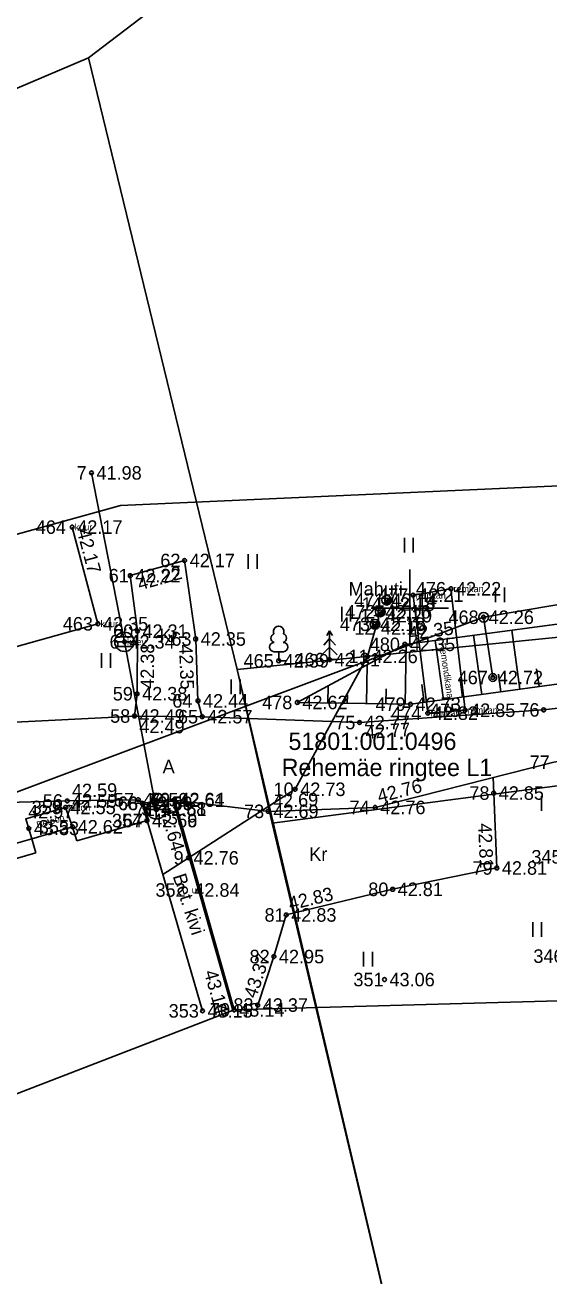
# Model space of a CAD drawing. Extents: x 505800 to 507326, y 6540058 to 6542128.
# Drawn here: x 506130.1 to 506157.2, y 6540215.4 to 6540280.2 of the extents above; entities that cross this region are included whole.
import ezdxf

# ---------------------------------------------------------------- set-up
doc = ezdxf.new("R2010")
doc.units = 0
for name, color, linetype in [('HALJASTUS', 7, 'Continuous'), ('HOONE', 7, 'Continuous'), ('HOONEDET', 7, 'Continuous'), ('KKAEV', 7, 'Continuous'), ('KORGUS-EH2000', 7, 'Continuous'), ('KTRASS', 7, 'Continuous'), ('MAAMUDEL', 7, 'Continuous'), ('MOOTKORG-EH2000', 7, 'Continuous'), ('MOOTMPUNKT', 7, 'Continuous'), ('MOOTNR', 7, 'Continuous'), ('MOOTPIIR', 7, 'Continuous'), ('MPOHULIIN', 7, 'Continuous'), ('PIIR', 7, 'Continuous'), ('POST', 7, 'Continuous'), ('PUU', 7, 'Continuous'), ('RAJATIS', 7, 'Continuous'), ('RELJEEF', 7, 'Continuous'), ('SKKAEV', 7, 'Continuous'), ('SKTRASS', 7, 'Continuous'), ('TEE', 7, 'Continuous'), ('VORK', 7, 'Continuous')]:
    doc.layers.add(name, color=color, linetype=linetype)

msp = doc.modelspace()

# ---------------------------------------------------------------- linework, layer by layer
at = {"layer": 'HALJASTUS'}
for p, q in [((506149.723, 6540253.631), (506149.723, 6540252.87)), ((506150.178, 6540253.631), (506150.178, 6540252.87)), ((506141.636, 6540252.79), (506141.636, 6540252.029)), ((506142.091, 6540252.79), (506142.091, 6540252.029)), ((506154.447, 6540251.067), (506154.447, 6540250.306)), ((506154.903, 6540251.067), (506154.903, 6540250.306)), ((506146.48, 6540250.066), (506146.48, 6540249.305)), ((506146.935, 6540250.066), (506146.935, 6540249.305)), ((506134.039, 6540247.662), (506134.039, 6540246.901)), ((506134.494, 6540247.662), (506134.494, 6540246.901)), ((506140.755, 6540246.3), (506140.755, 6540245.539)), ((506141.21, 6540246.3), (506141.21, 6540245.539)), ((506156.831, 6540240.242), (506156.831, 6540239.481)), ((506156.37, 6540233.722), (506156.37, 6540232.961)), ((506156.825, 6540233.722), (506156.825, 6540232.961)), ((506147.612, 6540232.18), (506147.612, 6540231.419)), ((506148.067, 6540232.18), (506148.067, 6540231.419))]:
    msp.add_line(p, q, dxfattribs=at)
at = {"layer": 'HOONE'}
for p, q in [((506132.539, 6540238.658), (506130.426, 6540238.044)), ((506132.539, 6540238.658), (506132.753, 6540237.924)), ((506130.426, 6540238.044), (506130.639, 6540237.309)), ((506130.639, 6540237.309), (506126.746, 6540236.177))]:
    msp.add_line(p, q, dxfattribs=at)
for points in [[(506132.518, 6540254.195), (506133.851, 6540249.184), (506123.465, 6540246.272), (506109.297, 6540242.297), (506097.771, 6540239.032), (506096.343, 6540244.043)], [(506132.753, 6540237.924), (506136.393, 6540238.982), (506139.264, 6540229.118)]]:
    msp.add_lwpolyline(points, dxfattribs=at)
at = {"layer": 'HOONEDET'}
msp.add_line((506125.837, 6540236.712), (506130.426, 6540238.044), dxfattribs=at)
at = {"layer": 'KKAEV'}
for p, q in [((506136.875, 6540239.064), (506136.875, 6540240.064)), ((506136.375, 6540239.564), (506137.375, 6540239.564))]:
    msp.add_line(p, q, dxfattribs=at)
msp.add_circle((506136.875, 6540239.564), 0.5, dxfattribs=at)
at = {"layer": 'KORGUS-EH2000'}
for centre in [(506133.515, 6540257.006), (506132.518, 6540254.195), (506138.341, 6540252.466), (506135.526, 6540251.679), (506152.137, 6540250.999), (506148.806, 6540250.407), (506150.181, 6540250.665), (506148.48, 6540249.801), (506133.851, 6540249.184), (506148.202, 6540249.16), (506153.828, 6540249.522), (506135.897, 6540248.799), (506138.913, 6540248.394), (506135.221, 6540248.25), (506149.749, 6540248.117), (506143.213, 6540247.263), (506145.85, 6540247.326), (506147.811, 6540247.492), (506154.303, 6540246.399), (506135.88, 6540245.556), (506139.032, 6540245.186), (506144.177, 6540245.106), (506150.046, 6540245.013), (506150.934, 6540244.549), (506152.867, 6540244.701), (506156.937, 6540244.719), (506135.743, 6540244.402), (506139.254, 6540244.367), (506147.401, 6540244.066), (506144.069, 6540240.604), (506132.254, 6540239.999), (506135.937, 6540240.063), (506137.811, 6540240.072), (506137.814, 6540240.039), (506154.348, 6540240.409), (506132.168, 6540239.664), (506136.14, 6540239.882), (506136.149, 6540239.864), (506136.86, 6540239.594), (506136.875, 6540239.564), (506142.677, 6540239.46), (506148.214, 6540239.664), (506132.539, 6540238.658), (506136.393, 6540238.982), (506136.395, 6540238.982), (506130.271, 6540238.577), (506138.541, 6540237.05), (506154.513, 6540236.525), (506149.115, 6540235.419), (506143.601, 6540234.09), (506142.965, 6540231.933), (506148.693, 6540230.741), (506139.264, 6540229.118), (506140.91, 6540229.168), (506142.127, 6540229.419)]:
    msp.add_circle(centre, 0.1, dxfattribs=at)
at = {"layer": 'KTRASS'}
msp.add_lwpolyline([(506148.371, 6540249.426), (506147.811, 6540247.492), (506144.069, 6540240.604), (506137.205, 6540236.191)], dxfattribs=at)
at = {"layer": 'MOOTMPUNKT'}
for centre in [(506133.515, 6540257.006), (506132.518, 6540254.195), (506138.341, 6540252.466), (506135.526, 6540251.679), (506152.137, 6540250.999), (506148.806, 6540250.407), (506150.181, 6540250.665), (506148.48, 6540249.801), (506133.851, 6540249.184), (506148.202, 6540249.16), (506153.828, 6540249.522), (506135.897, 6540248.799), (506138.913, 6540248.394), (506135.221, 6540248.25), (506149.749, 6540248.117), (506143.213, 6540247.263), (506145.85, 6540247.326), (506147.811, 6540247.492), (506154.303, 6540246.399), (506135.88, 6540245.556), (506139.032, 6540245.186), (506144.177, 6540245.106), (506150.046, 6540245.013), (506150.934, 6540244.549), (506152.867, 6540244.701), (506156.937, 6540244.719), (506135.743, 6540244.402), (506139.254, 6540244.367), (506147.401, 6540244.066), (506144.069, 6540240.604), (506132.254, 6540239.999), (506135.937, 6540240.063), (506137.811, 6540240.072), (506137.814, 6540240.039), (506154.348, 6540240.409), (506132.168, 6540239.664), (506136.14, 6540239.882), (506136.149, 6540239.864), (506136.86, 6540239.594), (506136.875, 6540239.564), (506142.677, 6540239.46), (506148.214, 6540239.664), (506132.539, 6540238.658), (506136.393, 6540238.982), (506136.395, 6540238.982), (506130.271, 6540238.577), (506138.541, 6540237.05), (506154.513, 6540236.525), (506149.115, 6540235.419), (506143.601, 6540234.09), (506142.965, 6540231.933), (506148.693, 6540230.741), (506139.264, 6540229.118), (506140.91, 6540229.168), (506142.127, 6540229.419)]:
    msp.add_circle(centre, 0.1, dxfattribs=at)
at = {"layer": 'MOOTPIIR'}
for points in [[(506083.03, 6540240.114), (506097.119, 6540244.795), (506135.023, 6540255.311), (506160.43, 6540256.455), (506171.091, 6540256.503), (506184.044, 6540258.184), (506197.806, 6540260.288), (506211.896, 6540262.383), (506227.932, 6540267.786), (506240.253, 6540270.959), (506245.955, 6540263.864)], [(506248.469, 6540250.071), (506234.931, 6540239.99), (506231.591, 6540236.406), (506193.196, 6540222.875), (506188.596, 6540225.549), (506168.901, 6540229.957), (506140.91, 6540229.168), (506108.07, 6540216.496), (506098.399, 6540223.506), (506079.917, 6540216.55)]]:
    msp.add_lwpolyline(points, dxfattribs=at)
at = {"layer": 'MPOHULIIN'}
msp.add_lwpolyline([(506112.189, 6540233.927), (506153.828, 6540249.522), (506196.936, 6540256.778), (506240.207, 6540264.027), (506283.784, 6540271.755), (506305.802, 6540315.044)], dxfattribs=at)
at = {"layer": 'PIIR'}
for points in [[(506133.36, 6540278.52), (506190.15, 6540321.81), (506215.95, 6540254.34), (506141.06, 6540246.81)], [(506075.94, 6540254.08), (506092.1, 6540260.96), (506133.36, 6540278.52), (506141.06, 6540246.81), (506150.17, 6540208.02), (506090.32, 6540182.64), (506081.75, 6540225.93), (506080.52, 6540231.87)]]:
    msp.add_lwpolyline(points, close=True, dxfattribs=at)
for points in [[(506272.39, 6540267.75), (506224.13, 6540249.92), (506208.53, 6540246.07), (506198.96, 6540244.45), (506187, 6540243.59), (506158.97, 6540240.95), (506142.88, 6540238.84), (506141.06, 6540246.81), (506215.95, 6540254.34), (506268.55, 6540273.9)], [(506028.99, 6540136.11), (506018.19, 6540200.68), (506049.36, 6540212.6), (506053.99, 6540200.79), (506052.51, 6540200.31), (506055.45, 6540190.69), (506062.61, 6540193.04), (506059.62, 6540202.68), (506057.79, 6540202.01), (506053.1, 6540214.07), (506081.75, 6540225.93), (506090.32, 6540182.64), (506150.17, 6540208.02), (506142.88, 6540238.84), (506158.97, 6540240.95), (506187, 6540243.59), (506198.96, 6540244.45), (506208.53, 6540246.07), (506224.13, 6540249.92), (506272.39, 6540267.75)]]:
    msp.add_lwpolyline(points, dxfattribs=at)
at = {"layer": 'POST'}
for p, q in [((506148.629, 6540250.23), (506148.983, 6540250.584)), ((506148.303, 6540249.625), (506148.657, 6540249.978)), ((506148.024, 6540248.984), (506148.378, 6540249.337))]:
    msp.add_line(p, q, dxfattribs=at)
msp.add_lwpolyline([(506154.303, 6540246.399), (506153.828, 6540249.522)], dxfattribs=at)
for centre, radius in [((506148.806, 6540250.407), 0.25), ((506148.48, 6540249.801), 0.25), ((506148.202, 6540249.16), 0.25), ((506153.828, 6540249.522), 0.25), ((506154.303, 6540246.399), 0.2)]:
    msp.add_circle(centre, radius, dxfattribs=at)
for centre, radius, start, end in [((506148.806, 6540250.407), 0.225, 224.85406, 45.03563), ((506148.806, 6540250.407), 0.2, 224.84272, 45.04698), ((506148.806, 6540250.407), 0.175, 224.82813, 45.06157), ((506148.806, 6540250.407), 0.15, 224.80867, 45.08103), ((506148.806, 6540250.407), 0.125, 224.78144, 45.10826), ((506148.806, 6540250.407), 0.1, 224.74058, 45.14911), ((506148.806, 6540250.407), 0.075, 224.67249, 45.2172), ((506148.806, 6540250.407), 0.05, 224.53632, 45.35338), ((506148.48, 6540249.801), 0.225, 224.85406, 45.03563), ((506148.48, 6540249.801), 0.2, 224.84272, 45.04698), ((506148.48, 6540249.801), 0.175, 224.82813, 45.06157), ((506148.48, 6540249.801), 0.15, 224.80867, 45.08103), ((506148.48, 6540249.801), 0.125, 224.78144, 45.10826), ((506148.48, 6540249.801), 0.1, 224.74058, 45.14911), ((506148.48, 6540249.801), 0.075, 224.67249, 45.2172), ((506148.48, 6540249.801), 0.05, 224.53632, 45.35338), ((506148.48, 6540249.801), 0.025, 224.12776, 45.76193), ((506148.806, 6540250.407), 0.025, 224.12776, 45.76193), ((506148.202, 6540249.16), 0.225, 224.85406, 45.03563), ((506148.202, 6540249.16), 0.2, 224.84272, 45.04698), ((506148.202, 6540249.16), 0.175, 224.82813, 45.06157), ((506148.202, 6540249.16), 0.15, 224.80867, 45.08103), ((506148.202, 6540249.16), 0.125, 224.78144, 45.10826), ((506148.202, 6540249.16), 0.1, 224.74058, 45.14911), ((506148.202, 6540249.16), 0.075, 224.67249, 45.2172), ((506148.202, 6540249.16), 0.05, 224.53632, 45.35338), ((506148.202, 6540249.16), 0.025, 224.12776, 45.76193)]:
    msp.add_arc(centre, radius, start, end, dxfattribs=at)
at = {"layer": 'PUU'}
for p, q in [((506145.85, 6540248.826), (506145.7, 6540248.576)), ((506146, 6540248.576), (506145.85, 6540248.826)), ((506145.85, 6540248.826), (506145.85, 6540247.326)), ((506145.85, 6540247.976), (506145.45, 6540247.576)), ((506145.85, 6540248.426), (506145.55, 6540248.076)), ((506146.15, 6540248.076), (506145.85, 6540248.426)), ((506146.25, 6540247.576), (506145.85, 6540247.976)), ((506143.454, 6540247.738), (506142.974, 6540247.738)), ((506143.213, 6540247.263), (506143.213, 6540247.738)), ((506143.594, 6540247.263), (506143.213, 6540247.263)), ((506146.21, 6540247.326), (506145.85, 6540247.326))]:
    msp.add_line(p, q, dxfattribs=at)
for centre, radius, start, end in [((506143.043, 6540248.436), 0.233, 109.02174, 253.14154), ((506143.213, 6540248.783), 0.277, 332.5799, 207.4201), ((506143.384, 6540248.436), 0.233, 286.85082, 70.98591), ((506142.976, 6540247.976), 0.238, 90.0016, 269.3953), ((506143.451, 6540247.976), 0.238, 270.6047, 89.9984)]:
    msp.add_arc(centre, radius, start, end, dxfattribs=at)
at = {"layer": 'RAJATIS'}
msp.add_lwpolyline([(506150.181, 6540250.665), (506150.934, 6540244.549), (506152.867, 6540244.701), (506152.137, 6540250.999)], close=True, dxfattribs=at)
at = {"layer": 'RELJEEF'}
for p, q in [((506153.727, 6540245.52), (506153.305, 6540248.587)), ((506155.708, 6540245.793), (506155.287, 6540248.85)), ((506149.762, 6540245.017), (506149.811, 6540248.125)), ((506151.746, 6540245.247), (506151.322, 6540248.325)), ((506147.762, 6540245.049), (506147.794, 6540247.061)), ((506154.718, 6540245.656), (506154.591, 6540246.575)), ((506156.699, 6540245.929), (506156.573, 6540246.845)), ((506145.762, 6540245.081), (506145.777, 6540245.971)), ((506150.755, 6540245.11), (506150.628, 6540246.036)), ((506152.736, 6540245.383), (506152.61, 6540246.305)), ((506146.762, 6540245.065), (506146.769, 6540245.5)), ((506148.762, 6540245.033), (506148.774, 6540245.805)), ((506144.763, 6540245.097), (506144.764, 6540245.196))]:
    msp.add_line(p, q, dxfattribs=at)
for points in [[(506186.229, 6540254.552), (506171.546, 6540250.385), (506161.646, 6540249.691), (506149.749, 6540248.117), (506144.177, 6540245.106)], [(506187.313, 6540250.618), (506176.15, 6540249.371), (506171.713, 6540248.272), (506161.906, 6540246.646), (506150.046, 6540245.013), (506144.177, 6540245.106)]]:
    msp.add_lwpolyline(points, dxfattribs=at)
at = {"layer": 'SKKAEV'}
for p, q in [((506135.651, 6540248.5), (506134.791, 6540248.5)), ((506134.721, 6540248.25), (506135.721, 6540248.25)), ((506135.651, 6540248), (506134.791, 6540248))]:
    msp.add_line(p, q, dxfattribs=at)
msp.add_circle((506135.221, 6540248.25), 0.5, dxfattribs=at)
at = {"layer": 'SKTRASS'}
msp.add_lwpolyline([(506133.515, 6540257.006), (506135.221, 6540248.25), (506136.86, 6540239.594)], dxfattribs=at)
at = {"layer": 'TEE'}
for points in [[(506250.031, 6540264.042), (506237.432, 6540259.066), (506223.872, 6540254.219), (506212.634, 6540251.013), (506200.022, 6540248.8), (506187.383, 6540247.629), (506174.426, 6540246.673), (506168.123, 6540246.063), (506162.988, 6540245.422), (506156.937, 6540244.719), (506147.401, 6540244.066), (506139.254, 6540244.367), (506135.743, 6540244.402), (506126.133, 6540243.916), (506116.327, 6540241.664), (506104.313, 6540238.326), (506099.073, 6540236.742), (506091.024, 6540234.378), (506084.768, 6540232.16)], [(506250.904, 6540261.782), (506238.366, 6540256.809), (506224.827, 6540251.952), (506213.198, 6540248.536), (506200.494, 6540246.321), (506187.779, 6540245.271), (506174.602, 6540244.231), (506168.346, 6540243.484), (506163.12, 6540242.933), (506157.471, 6540242.007), (506148.214, 6540239.664), (506142.677, 6540239.46), (506137.814, 6540240.039)], [(506139.254, 6540244.367), (506139.032, 6540245.186), (506138.913, 6540248.394), (506138.341, 6540252.466), (506135.526, 6540251.679), (506135.897, 6540248.799), (506135.88, 6540245.556), (506135.743, 6540244.402)], [(506142.127, 6540229.419), (506142.965, 6540231.933), (506143.601, 6540234.09), (506149.115, 6540235.419), (506154.513, 6540236.525), (506154.348, 6540240.409), (506154.329, 6540241.211)], [(506136.149, 6540239.864), (506135.937, 6540240.063), (506132.254, 6540239.999), (506126.638, 6540239.842), (506117.049, 6540238.049), (506105.059, 6540234.886), (506099.56, 6540233.572), (506092.451, 6540231.789), (506085.515, 6540229.625), (506076.748, 6540225.83), (506064.781, 6540220.419), (506053.702, 6540216.033), (506042.573, 6540211.964), (506030.369, 6540207.528), (506023.645, 6540204.818), (506020.115, 6540202.573), (506018.326, 6540200.153), (506016.859, 6540196.696), (506016.712, 6540193.498), (506017.316, 6540188.473)], [(506140.91, 6540229.168), (506137.811, 6540240.072), (506136.14, 6540239.882), (506136.395, 6540238.982)], [(506132.539, 6540238.658), (506132.168, 6540239.664), (506130.113, 6540239.081), (506130.426, 6540238.044)], [(506140.833, 6540229.146), (506137.752, 6540239.985), (506136.243, 6540239.813), (506136.472, 6540239.004), (506136.395, 6540238.982)]]:
    msp.add_lwpolyline(points, dxfattribs=at)
at = {"layer": 'VORK'}
for p, q in [((506150, 6540252), (506150, 6540248)), ((506148, 6540250), (506152, 6540250))]:
    msp.add_line(p, q, dxfattribs=at)

# ---------------------------------------------------------------- texts
at = {"layer": 'KORGUS-EH2000'}
for s, rotation, p in [(' 42.17', 284.89789, (506132.687, 6540254.24)), (' 42.22', 15.62715, (506135.762, 6540250.836)), (' 42.35', 7.53501, (506149.727, 6540248.291)), (' 42.38', 89.70843, (506136.755, 6540245.552)), (' 42.35', 272.12083, (506138.039, 6540248.362)), (' 42.49', 359.42558, (506135.734, 6540243.527)), (' 42.77', 3.91269, (506147.461, 6540243.193)), (' 42.59', 1.00192, (506132.251, 6540240.174)), (' 42.76', 14.19953, (506148.171, 6540239.834)), (' 42.69', 2.10984, (506142.67, 6540239.635)), (' 42.64', 285.86438, (506136.969, 6540239.833)), (' 42.81', 272.42534, (506153.528, 6540239.089)), (' 42.83', 13.54771, (506143.56, 6540234.261)), (' 43.37', 71.56642, (506141.961, 6540229.474)), (' 43.14', 285.86438, (506139.267, 6540231.378))]:
    msp.add_text(s, height=0.7, rotation=rotation, dxfattribs=at).set_placement(p)
for s, p in [(' 42.26', (506153.828, 6540249.172)), (' 42.39', (506143.213, 6540246.913)), (' 43.06', (506148.693, 6540230.391))]:
    msp.add_text(s, height=0.7, dxfattribs=at).set_placement(p)
at = {"layer": 'MAAMUDEL'}
for s, p in [(' kuur', (506132.518, 6540254.02)), (' remkan', (506152.137, 6540250.824)), (' remkan', (506150.181, 6540250.49)), (' kuur', (506133.851, 6540249.009)), (' kaev', (506135.221, 6540248.075)), (' remkan', (506150.934, 6540244.374)), (' remkan', (506152.867, 6540244.526)), (' beton', (506132.168, 6540239.489)), (' uk', (506138.581, 6540235.208))]:
    msp.add_text(s, height=0.35, dxfattribs=at).set_placement(p)
at = {"layer": 'MOOTKORG-EH2000'}
for s, p in [(' 41.98', (506133.515, 6540256.656)), (' 42.17', (506132.518, 6540253.845)), (' 42.17', (506138.341, 6540252.116)), (' 42.22', (506135.526, 6540251.329)), (' 42.22', (506152.137, 6540250.649)), (' 42.18', (506148.701, 6540249.855)), (' 42.14', (506148.806, 6540250.057)), (' 42.21', (506150.181, 6540250.315)), (' 42.16', (506148.48, 6540249.451)), (' 42.20', (506148.548, 6540249.252)), (' 42.26', (506153.828, 6540249.172)), (' 42.35', (506133.851, 6540248.834)), (' 42.31', (506135.897, 6540248.449)), (' 42.18', (506148.202, 6540248.81)), (' 42.19', (506148.254, 6540248.621)), (' 42.34', (506135.221, 6540247.9)), (' 42.35', (506138.913, 6540248.044)), (' 42.26', (506147.811, 6540247.142)), (' 42.35', (506149.749, 6540247.767)), (' 42.39', (506143.213, 6540246.913)), (' 42.31', (506145.85, 6540246.976)), (' 42.72', (506154.303, 6540246.049)), (' 42.38', (506135.88, 6540245.207)), (' 42.44', (506139.032, 6540244.836)), (' 42.62', (506144.177, 6540244.756)), (' 42.73', (506150.046, 6540244.663)), (' 42.49', (506135.743, 6540244.052)), (' 42.57', (506139.254, 6540244.017)), (' 42.82', (506150.934, 6540244.199)), (' 42.85', (506152.867, 6540244.351)), (' 42.77', (506147.401, 6540243.716)), (' 42.73', (506144.069, 6540240.254)), (' 42.85', (506154.348, 6540240.059)), (' 42.59', (506132.254, 6540239.649)), (' 42.59', (506135.937, 6540239.713)), (' 42.59', (506136.14, 6540239.532)), (' 42.56', (506136.149, 6540239.514)), (' 42.64', (506137.811, 6540239.722)), (' 42.61', (506137.814, 6540239.689)), (' 42.97', (506129.978, 6540239.098)), (' 42.55', (506132.168, 6540239.314)), (' 42.58', (506136.86, 6540239.244)), (' 42.61', (506136.875, 6540239.214)), (' 42.69', (506142.677, 6540239.11)), (' 42.76', (506148.214, 6540239.314)), (' 43.33', (506130.271, 6540238.227)), (' 42.62', (506132.539, 6540238.308)), (' 42.66', (506136.393, 6540238.632)), (' 42.69', (506136.395, 6540238.632)), (' 42.76', (506138.541, 6540236.7)), (' 42.81', (506154.513, 6540236.175)), (' 42.84', (506138.581, 6540235.033)), (' 42.81', (506149.115, 6540235.069)), (' 42.83', (506143.601, 6540233.74)), (' 42.95', (506142.965, 6540231.583)), (' 43.06', (506148.693, 6540230.391)), (' 43.37', (506142.127, 6540229.069)), (' 43.15', (506139.264, 6540228.768)), (' 43.14', (506140.91, 6540228.818))]:
    msp.add_text(s, height=0.7, dxfattribs=at).set_placement(p)
at = {"layer": 'MOOTNR'}
for s, p in [('7 ', (506132.746, 6540256.656)), ('464 ', (506130.628, 6540253.845)), ('62 ', (506137.081, 6540252.116)), ('61 ', (506134.406, 6540251.329)), ('476 ', (506150.317, 6540250.649)), ('471 ', (506147.126, 6540250.057)), ('14 ', (506147.511, 6540249.855)), ('477 ', (506148.361, 6540250.315)), ('472 ', (506146.66, 6540249.451)), ('13 ', (506147.428, 6540249.252)), ('468 ', (506152.008, 6540249.172)), ('463 ', (506132.031, 6540248.834)), ('60 ', (506134.637, 6540248.449)), ('473 ', (506146.382, 6540248.81)), ('12 ', (506147.134, 6540248.621)), ('6 ', (506134.451, 6540247.9)), ('63 ', (506137.653, 6540248.044)), ('11 ', (506146.831, 6540247.142)), ('480 ', (506147.93, 6540247.767)), ('465 ', (506141.394, 6540246.913)), ('466 ', (506144.03, 6540246.976)), ('467 ', (506152.484, 6540246.049)), ('59 ', (506134.62, 6540245.207)), ('64 ', (506137.702, 6540244.836)), ('478 ', (506142.357, 6540244.756)), ('479 ', (506148.227, 6540244.663)), ('58 ', (506134.483, 6540244.052)), ('65 ', (506137.994, 6540244.017)), ('474 ', (506149.044, 6540244.199)), ('475 ', (506151.047, 6540244.351)), ('76 ', (506155.677, 6540244.369)), ('75 ', (506146.141, 6540243.716)), ('77 ', (506156.211, 6540241.656)), ('10 ', (506142.949, 6540240.254)), ('78 ', (506153.088, 6540240.059)), ('56 ', (506130.994, 6540239.649)), ('57 ', (506134.677, 6540239.713)), ('68 ', (506134.88, 6540239.532)), ('66 ', (506134.889, 6540239.514)), ('69 ', (506136.551, 6540239.722)), ('72 ', (506136.554, 6540239.689)), ('359 ', (506130.418, 6540239.314)), ('71 ', (506135.755, 6540239.214)), ('5 ', (506136.09, 6540239.244)), ('73 ', (506141.417, 6540239.11)), ('74 ', (506146.884, 6540239.314)), ('355 ', (506130.789, 6540238.308)), ('354 ', (506134.573, 6540238.632)), ('67 ', (506135.135, 6540238.632)), ('345 ', (506156.301, 6540236.755)), ('9 ', (506137.771, 6540236.7)), ('79 ', (506153.253, 6540236.175)), ('352 ', (506136.831, 6540235.033)), ('80 ', (506147.855, 6540235.069)), ('81 ', (506142.481, 6540233.74)), ('82 ', (506141.705, 6540231.583)), ('346 ', (506156.405, 6540231.607)), ('351 ', (506147.083, 6540230.391)), ('83 ', (506140.867, 6540229.069)), ('353 ', (506137.514, 6540228.768)), ('70 ', (506139.65, 6540228.818))]:
    msp.add_text(s, height=0.7, dxfattribs=at).set_placement(p)
at = {"layer": 'PIIR'}
for s, p in [('51801:001:0496', (506143.72, 6540242.643)), ('Rehemäe ringtee L1', (506143.368, 6540241.288))]:
    msp.add_text(s, height=0.9, dxfattribs=at).set_placement(p)
at = {"layer": 'RAJATIS'}
msp.add_text('Mahuti', height=0.7, dxfattribs=at).set_placement((506146.833, 6540250.645))
msp.add_text('Remondikanal', height=0.35, rotation=278.43576, dxfattribs=at).set_placement((506151.517, 6540248.158))
at = {"layer": 'TEE'}
for s, p in [('Kr', (506137.038, 6540248.236)), ('A', (506137.201, 6540241.437)), ('Kr', (506144.795, 6540236.893))]:
    msp.add_text(s, height=0.7, dxfattribs=at).set_placement(p)
for s, height, rotation, p in [('Betoon', 0.35, 16.14147, (506130.729, 6540238.574)), ('Bet. kivi', 0.7, 287.89263, (506137.718, 6540236.104))]:
    msp.add_text(s, height=height, rotation=rotation, dxfattribs=at).set_placement(p)

doc.saveas('drawing.dxf')
